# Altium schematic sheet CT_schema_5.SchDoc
size 300 x 247 mm
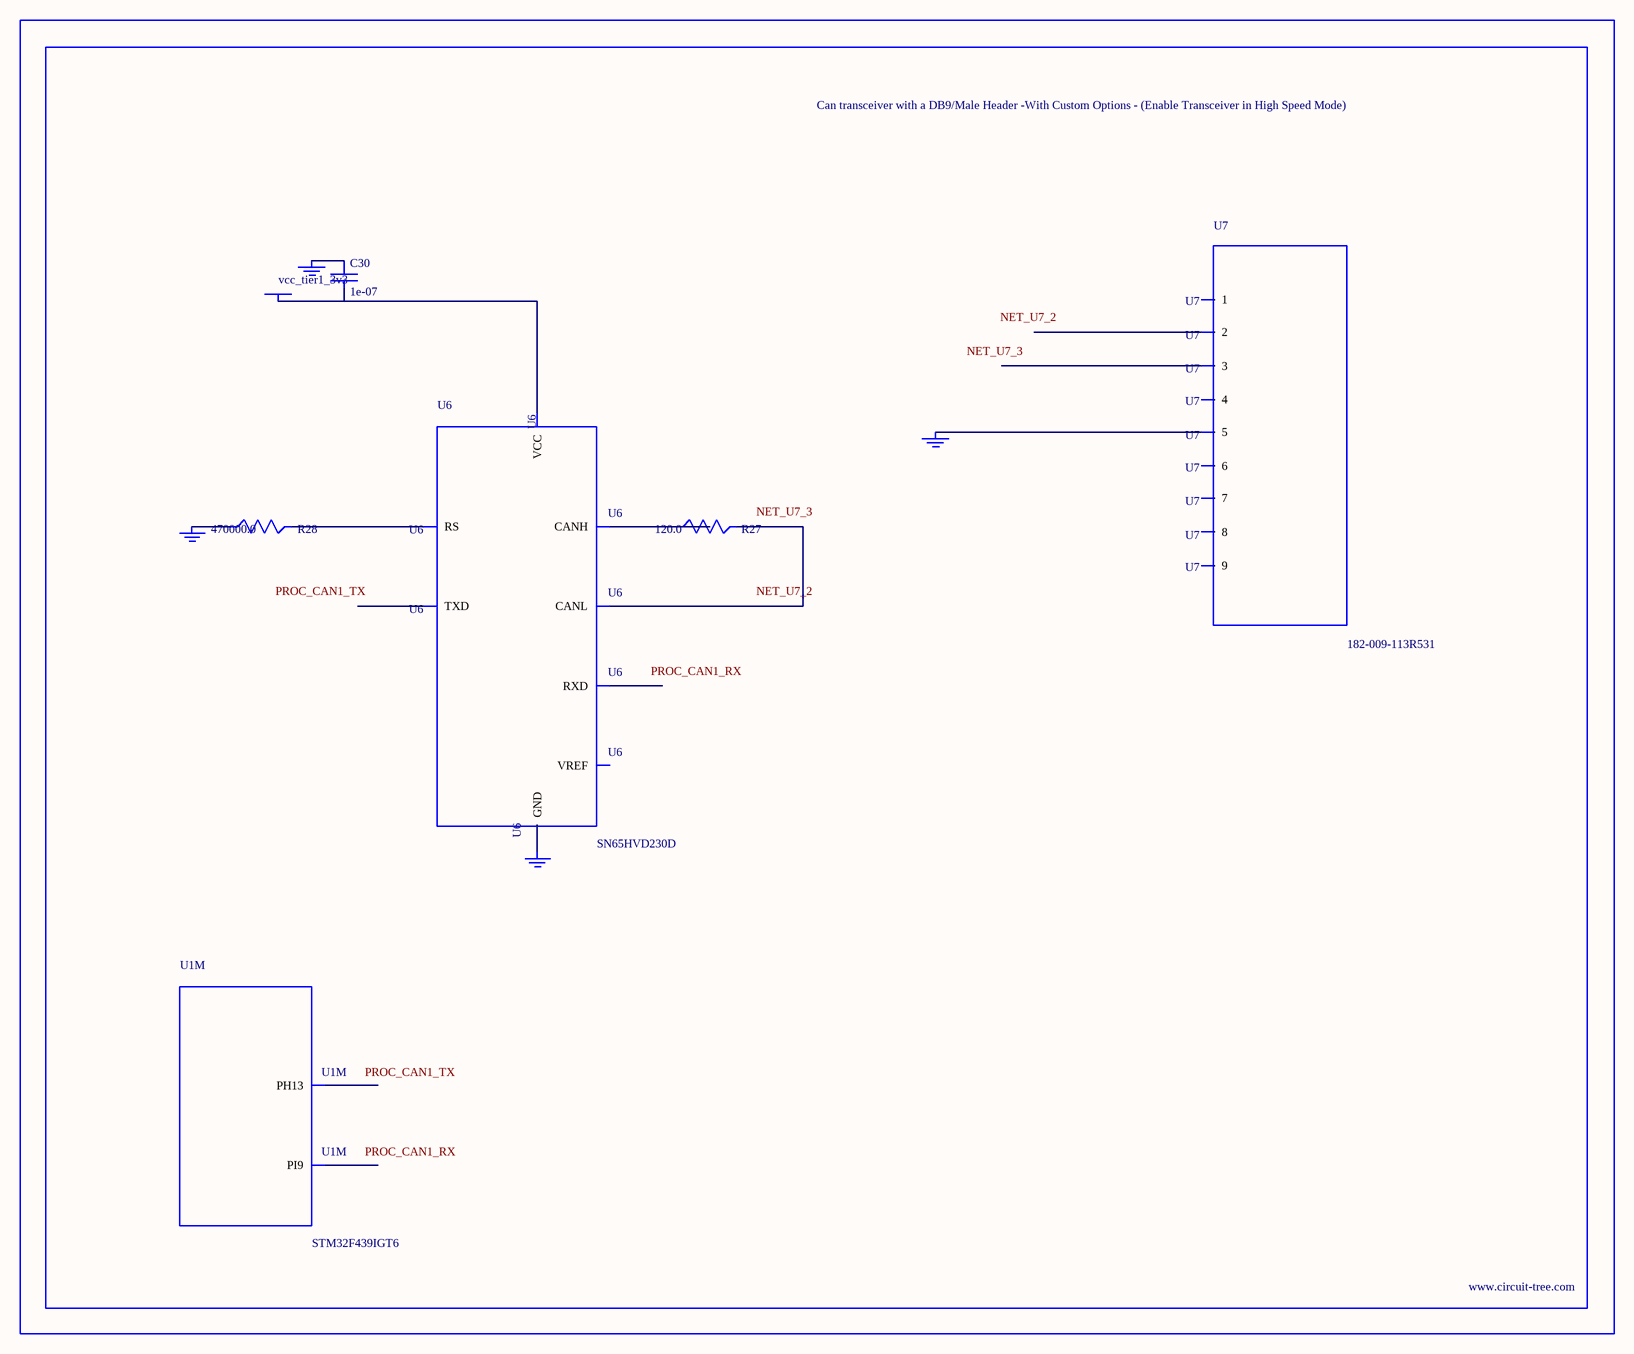
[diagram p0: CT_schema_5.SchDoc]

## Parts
BORDER4  (no value)
C30  1e-07  [C0402]
GND_INSTANCE_4_0  (no value)
GND_INSTANCE_4_1  (no value)
GND_INSTANCE_4_2  (no value)
GND_INSTANCE_4_3  (no value)
POWER_INSTANCE_4_0  vcc_tier1_3v3
R27  120.0  [R0603]
R28  470000.0  [R0603]
U1  STM32F439IGT6  [LQFP176]  (part M of 14)
U6  SN65HVD230D  [SOIC-8]
U7  182-009-113R531  [182-009-MALE]

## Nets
NetC30_1: C30.1 GND_INSTANCE_4_0.0(GND)
NetC30_2: C30.2 POWER_INSTANCE_4_0.0(PWR) U6.3(VCC)
NetGND_INSTANCE_4_1_0: GND_INSTANCE_4_1.0(GND) R28.1
NetGND_INSTANCE_4_2_0: GND_INSTANCE_4_2.0(GND) U6.2(GND)
NetGND_INSTANCE_4_3_0: GND_INSTANCE_4_3.0(GND) U7.5
NetR27_1: R27.1 U6.7(CANH)
NetR27_2: R27.2 U6.6(CANL)
NetR28_2: R28.2 U6.8(RS)

Not connected (* = marked no-connect by the designer): U1 11(PI9) 128(PH13); U6 1(TXD) 4(RXD) 5(VREF); U7 1 2 3 4 6 7 8 9

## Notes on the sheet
- Labels drawn without touching a wire or pin: NET_U7_2, NET_U7_3, PROC_CAN1_RX, PROC_CAN1_TX

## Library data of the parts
BORDER4 = BORDER_PAGE4
C30 = C0402C104K3RACTU
GND_INSTANCE_4_0-GND_INSTANCE_4_3 = GND
POWER_INSTANCE_4_0 = PWR
R27 = RC0603JR-07120RL
R28 = RC0603JR-07470KL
